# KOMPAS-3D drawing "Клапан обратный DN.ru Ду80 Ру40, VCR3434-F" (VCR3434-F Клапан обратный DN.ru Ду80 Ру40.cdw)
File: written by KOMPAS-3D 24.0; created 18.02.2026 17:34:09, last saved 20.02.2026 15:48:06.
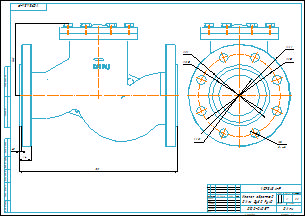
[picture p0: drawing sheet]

Document properties: art: D100-04057; Автор: R2D2; Форматы листов документа: A2; Полное имя файла: VCR3434-F Клапан обратный DN.ru Ду80 Ру40.m3d; Масса: 22; Наименование: Клапан обратный DN.ru Ду80 Ру40; Количество листов документа: 1; Примечание: D100-04057

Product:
- Part/product: Клапан обратный DN.ru Ду80 Ру40  | designation VCR3434-F
    Масса: 22
    Раздел спецификации: Прочие изделия
    Примечание: D100-04057
    additional columns: D100-04057

Views: Вид 1, Спереди, Проекционный вид 2
Referenced files in E:\Работа\Зайцев\VCR3434-F Клапан обратный DN.ru Ду15-300\DN80\: VCR3434-F Клапан обратный DN.ru Ду80 Ру40.m3d
Referenced files in E:\Работа\Зайцев\Для компаса\: чертеж DN.ru А3.cdt
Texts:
  VCR3434-F
  чертеж DN.ru А3.cdt
  Клапан обратный
  DN.ru Ду80 Ру40
  prop
  Клапан обратный DN.ru Ду80 Ру40
  VCR3434-F Клапан обратный DN.ru Ду80 Ру40
Dimensions and other numbers on the sheet: 0; 3; 2; 4; 200; 160; 18; 8 отв.; 80; 106; 120; 4,5; 24; 310; 140; 1:1; 1; 22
